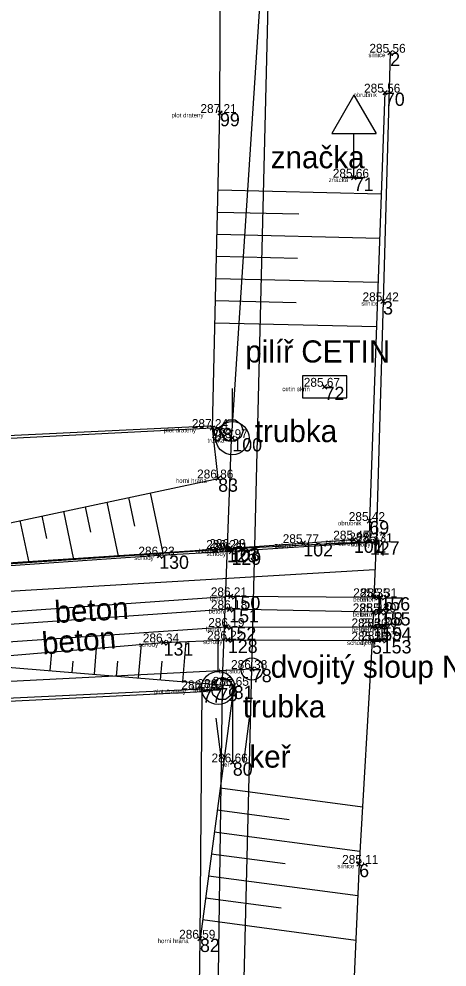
# Model space of a CAD drawing. Extents: x -456675 to -456278, y -1112395 to -1112217.
# Drawn here: x -456337.38 to -456327.72, y -1112310.69 to -1112289.29 of the extents above; entities that cross this region are included whole.
import ezdxf

# ---------------------------------------------------------------- set-up
doc = ezdxf.new("R2010")
doc.units = 0
for name, color, linetype in [('Cislo_bodu', 7, 'Continuous'), ('g_beton', 7, 'Continuous'), ('g_CETIN', 7, 'Continuous'), ('g_dopravni_znaceni', 7, 'Continuous'), ('g_elektrina', 7, 'Continuous'), ('g_katastr_stabilizace', 7, 'Continuous'), ('g_komunikace', 7, 'Continuous'), ('g_obrubnik', 7, 'Continuous'), ('g_ploty', 7, 'Continuous'), ('g_schody', 7, 'Continuous'), ('g_terenni_hrany', 7, 'Continuous'), ('g_vegetace', 7, 'Continuous'), ('g_zabradli', 7, 'Continuous'), ('Katastralni_mapa', 7, 'Continuous'), ('Kod_bodu', 7, 'Continuous'), ('Vyska_bodu', 7, 'Continuous'), ('Znacka_bodu', 7, 'Continuous')]:
    doc.layers.add(name, color=color, linetype=linetype)

msp = doc.modelspace()

# ---------------------------------------------------------------- linework, layer by layer
at = {"layer": 'g_beton'}
for points in [[(-456344.443, -1112303.14), (-456341.853, -1112302.97), (-456340.193, -1112302.85), (-456332.603, -1112302.32), (-456329.373, -1112302.34)], [(-456329.383, -1112302.68), (-456332.633, -1112302.61), (-456340.183, -1112303.14), (-456341.853, -1112303.27), (-456344.443, -1112303.43)], [(-456344.433, -1112303.79), (-456341.843, -1112303.66), (-456340.153, -1112303.52), (-456332.693, -1112303.01), (-456329.403, -1112303.02)]]:
    msp.add_lwpolyline(points, dxfattribs=at)
at = {"layer": 'g_CETIN'}
msp.add_lwpolyline([(-456330.983, -1112297.84), (-456329.983, -1112297.84), (-456329.983, -1112297.34), (-456330.983, -1112297.34)], close=True, dxfattribs=at)
at = {"layer": 'g_dopravni_znaceni'}
for p, q in [((-456329.823, -1112291.004), (-456330.323, -1112291.87)), ((-456329.823, -1112291.004), (-456329.323, -1112291.87)), ((-456330.323, -1112291.87), (-456329.323, -1112291.87)), ((-456329.823, -1112292.87), (-456329.823, -1112291.87)), ((-456330.073, -1112292.87), (-456329.573, -1112292.87))]:
    msp.add_line(p, q, dxfattribs=at)
at = {"layer": 'g_elektrina'}
msp.add_line((-456361.003, -1112305.42), (-456332.123, -1112303.96), dxfattribs=at)
msp.add_lwpolyline([(-456332.513, -1112319.78), (-456332.123, -1112303.96), (-456331.453, -1112276.72)], dxfattribs=at)
msp.add_circle((-456332.123, -1112303.96), 0.25, dxfattribs=at)
at = {"layer": 'g_katastr_stabilizace'}
for p, q in [((-456332.563, -1112298.376), (-456332.563, -1112297.626)), ((-456332.883, -1112304.015), (-456332.883, -1112303.265))]:
    msp.add_line(p, q, dxfattribs=at)
for centre, radius in [((-456332.563, -1112298.751), 0.375), ((-456332.563, -1112298.751), 0.0005), ((-456332.883, -1112304.39), 0.375), ((-456332.883, -1112304.39), 0.0005)]:
    msp.add_circle(centre, radius, dxfattribs=at)
at = {"layer": 'g_komunikace'}
msp.add_lwpolyline([(-456329.003, -1112290.05), (-456329.163, -1112295.66), (-456329.323, -1112301.1), (-456329.373, -1112302.34), (-456329.223, -1112302.34), (-456329.213, -1112302.68), (-456329.383, -1112302.68), (-456329.403, -1112303.02), (-456329.193, -1112303.02), (-456329.193, -1112303.31), (-456329.413, -1112303.32), (-456329.703, -1112308.36), (-456330.013, -1112315.33)], dxfattribs=at)
at = {"layer": 'g_obrubnik'}
for p, q in [((-456329.123, -1112290.95), (-456329.473, -1112300.62)), ((-456329.473, -1112300.62), (-456329.463, -1112301.08))]:
    msp.add_line(p, q, dxfattribs=at)
msp.add_lwpolyline([(-456347.483, -1112302.26), (-456344.233, -1112302.04), (-456332.683, -1112301.25), (-456329.463, -1112301.08)], dxfattribs=at)
at = {"layer": 'g_ploty'}
for points in [[(-456357.813, -1112299.7), (-456346.273, -1112299.18), (-456339.333, -1112298.84), (-456333.013, -1112298.52), (-456332.843, -1112291.41), (-456332.833, -1112287.66)], [(-456333.393, -1112317.5), (-456333.293, -1112310.05), (-456333.243, -1112304.42), (-456339.393, -1112304.71), (-456347.913, -1112305.1), (-456359.473, -1112305.79)]]:
    msp.add_lwpolyline(points, dxfattribs=at)
at = {"layer": 'g_schody'}
msp.add_line((-456329.348, -1112301.72), (-456344.478, -1112302.62), dxfattribs=at)
msp.add_lwpolyline([(-456329.323, -1112301.1), (-456332.583, -1112301.31), (-456334.213, -1112301.4), (-456340.273, -1112301.82), (-456341.953, -1112301.93), (-456344.513, -1112302.1), (-456344.443, -1112303.14), (-456344.443, -1112303.43), (-456344.433, -1112303.79), (-456344.453, -1112304.12), (-456341.853, -1112303.96), (-456340.143, -1112303.85), (-456339.183, -1112303.79), (-456334.113, -1112303.36), (-456332.663, -1112303.3), (-456329.413, -1112303.32)], dxfattribs=at)
at = {"layer": 'g_terenni_hrany'}
for p, q in [((-456329.206, -1112293.241), (-456332.885, -1112293.153)), ((-456331.061, -1112293.697), (-456332.897, -1112293.653)), ((-456329.242, -1112294.24), (-456332.909, -1112294.153)), ((-456331.091, -1112294.696), (-456332.921, -1112294.653)), ((-456329.279, -1112295.24), (-456332.933, -1112295.152)), ((-456331.121, -1112295.696), (-456332.945, -1112295.652)), ((-456329.315, -1112296.239), (-456332.957, -1112296.152)), ((-456334.122, -1112301.348), (-456334.412, -1112299.986)), ((-456335.756, -1112300.875), (-456335.879, -1112300.298)), ((-456335.13, -1112301.417), (-456335.39, -1112300.194)), ((-456334.764, -1112300.736), (-456334.901, -1112300.09)), ((-456336.749, -1112301.013), (-456336.857, -1112300.506)), ((-456336.137, -1112301.486), (-456336.368, -1112300.402)), ((-456337.145, -1112301.555), (-456337.346, -1112300.61)), ((-456335.635, -1112303.489), (-456335.684, -1112304.079)), ((-456334.624, -1112303.403), (-456334.687, -1112304.162)), ((-456333.615, -1112303.339), (-456333.69, -1112304.244)), ((-456336.645, -1112303.575), (-456336.68, -1112303.997)), ((-456336.161, -1112303.785), (-456336.182, -1112304.038)), ((-456335.157, -1112303.783), (-456335.185, -1112304.121)), ((-456334.154, -1112303.782), (-456334.189, -1112304.203)), ((-456329.63, -1112307.08), (-456332.841, -1112306.653)), ((-456331.283, -1112307.365), (-456332.907, -1112307.149)), ((-456329.687, -1112308.082), (-456332.973, -1112307.644)), ((-456331.376, -1112308.361), (-456333.039, -1112308.14)), ((-456329.736, -1112309.084), (-456333.105, -1112308.636)), ((-456331.464, -1112309.358), (-456333.171, -1112309.131)), ((-456329.78, -1112310.087), (-456333.237, -1112309.627))]:
    msp.add_line(p, q, dxfattribs=at)
for points in [[(-456341.973, -1112301.85), (-456338.143, -1112300.78), (-456332.883, -1112299.66), (-456333.013, -1112298.52)], [(-456339.183, -1112303.79), (-456332.533, -1112304.34), (-456333.293, -1112310.05)]]:
    msp.add_lwpolyline(points, dxfattribs=at)
at = {"layer": 'g_vegetace'}
for p, q in [((-456332.553, -1112306.07), (-456332.553, -1112304.57)), ((-456332.803, -1112306.07), (-456332.928, -1112305.07)), ((-456332.303, -1112306.07), (-456332.178, -1112305.07))]:
    msp.add_line(p, q, dxfattribs=at)
at = {"layer": 'g_zabradli'}
msp.add_lwpolyline([(-456344.563, -1112302.04), (-456341.973, -1112301.85), (-456332.613, -1112301.23), (-456330.963, -1112301.12), (-456329.823, -1112301.04)], dxfattribs=at)
at = {"layer": 'Katastralni_mapa'}
for points in [[(-456331.863, -1112287.61), (-456332.573, -1112298.58)], [(-456333.073, -1112298.48), (-456362.193, -1112299.87)], [(-456332.573, -1112298.58), (-456333.073, -1112298.48)], [(-456332.793, -1112304.41), (-456332.573, -1112298.58)], [(-456332.598, -1112298.58), (-456332.548, -1112298.58)], [(-456347.903, -1112305.2), (-456333.213, -1112304.47)], [(-456333.213, -1112304.47), (-456332.793, -1112304.41)], [(-456332.793, -1112304.41), (-456333.173, -1112331.27)], [(-456332.818, -1112304.41), (-456332.768, -1112304.41)]]:
    msp.add_lwpolyline(points, dxfattribs=at)
for points in [[(-456332.498, -1112298.34), (-456332.373, -1112298.435), (-456332.323, -1112298.58), (-456332.373, -1112298.725), (-456332.498, -1112298.82), (-456332.648, -1112298.82), (-456332.773, -1112298.725), (-456332.823, -1112298.58), (-456332.773, -1112298.435), (-456332.648, -1112298.34)], [(-456332.718, -1112304.17), (-456332.593, -1112304.265), (-456332.543, -1112304.41), (-456332.593, -1112304.555), (-456332.718, -1112304.65), (-456332.868, -1112304.65), (-456332.993, -1112304.555), (-456333.043, -1112304.41), (-456332.993, -1112304.265), (-456332.868, -1112304.17)]]:
    msp.add_lwpolyline(points, close=True, dxfattribs=at)
at = {"layer": 'Znacka_bodu'}
for p, q in [((-456329.003, -1112290.05), (-456329.053, -1112290)), ((-456329.003, -1112290.05), (-456328.953, -1112290)), ((-456329.003, -1112290.05), (-456329.053, -1112290.1)), ((-456329.003, -1112290.05), (-456328.953, -1112290.1)), ((-456329.123, -1112290.95), (-456329.173, -1112290.9)), ((-456329.123, -1112290.95), (-456329.173, -1112291)), ((-456329.123, -1112290.95), (-456329.073, -1112290.9)), ((-456329.123, -1112290.95), (-456329.073, -1112291)), ((-456332.843, -1112291.41), (-456332.893, -1112291.36)), ((-456332.843, -1112291.41), (-456332.893, -1112291.46)), ((-456332.843, -1112291.41), (-456332.793, -1112291.36)), ((-456332.843, -1112291.41), (-456332.793, -1112291.46)), ((-456329.823, -1112292.87), (-456329.873, -1112292.82)), ((-456329.823, -1112292.87), (-456329.873, -1112292.92)), ((-456329.823, -1112292.87), (-456329.773, -1112292.82)), ((-456329.823, -1112292.87), (-456329.773, -1112292.92)), ((-456329.163, -1112295.66), (-456329.213, -1112295.61)), ((-456329.163, -1112295.66), (-456329.213, -1112295.71)), ((-456329.163, -1112295.66), (-456329.113, -1112295.61)), ((-456329.163, -1112295.66), (-456329.113, -1112295.71)), ((-456330.483, -1112297.59), (-456330.533, -1112297.54)), ((-456330.483, -1112297.59), (-456330.533, -1112297.64)), ((-456330.483, -1112297.59), (-456330.433, -1112297.54)), ((-456330.483, -1112297.59), (-456330.433, -1112297.64)), ((-456333.013, -1112298.52), (-456333.063, -1112298.47)), ((-456333.013, -1112298.52), (-456333.063, -1112298.57)), ((-456333.013, -1112298.52), (-456332.963, -1112298.47)), ((-456333.013, -1112298.52), (-456332.963, -1112298.57)), ((-456332.563, -1112298.75), (-456332.613, -1112298.7)), ((-456332.563, -1112298.75), (-456332.613, -1112298.8)), ((-456332.563, -1112298.75), (-456332.513, -1112298.7)), ((-456332.563, -1112298.75), (-456332.513, -1112298.8)), ((-456332.883, -1112299.66), (-456332.933, -1112299.61)), ((-456332.883, -1112299.66), (-456332.833, -1112299.61)), ((-456332.883, -1112299.66), (-456332.933, -1112299.71)), ((-456332.883, -1112299.66), (-456332.833, -1112299.71)), ((-456329.473, -1112300.62), (-456329.523, -1112300.57)), ((-456329.473, -1112300.62), (-456329.523, -1112300.67)), ((-456329.473, -1112300.62), (-456329.423, -1112300.57)), ((-456329.473, -1112300.62), (-456329.423, -1112300.67)), ((-456330.963, -1112301.12), (-456331.013, -1112301.07)), ((-456330.963, -1112301.12), (-456331.013, -1112301.17)), ((-456330.963, -1112301.12), (-456330.913, -1112301.07)), ((-456330.963, -1112301.12), (-456330.913, -1112301.17)), ((-456329.823, -1112301.04), (-456329.873, -1112300.99)), ((-456329.823, -1112301.04), (-456329.873, -1112301.09)), ((-456329.823, -1112301.04), (-456329.773, -1112300.99)), ((-456329.823, -1112301.04), (-456329.773, -1112301.09)), ((-456329.463, -1112301.08), (-456329.513, -1112301.03)), ((-456329.463, -1112301.08), (-456329.513, -1112301.13)), ((-456329.463, -1112301.08), (-456329.413, -1112301.03)), ((-456329.463, -1112301.08), (-456329.413, -1112301.13)), ((-456329.323, -1112301.1), (-456329.373, -1112301.05)), ((-456329.323, -1112301.1), (-456329.373, -1112301.15)), ((-456329.323, -1112301.1), (-456329.273, -1112301.05)), ((-456329.323, -1112301.1), (-456329.273, -1112301.15)), ((-456334.213, -1112301.4), (-456334.263, -1112301.35)), ((-456334.213, -1112301.4), (-456334.163, -1112301.35)), ((-456332.683, -1112301.25), (-456332.733, -1112301.2)), ((-456332.683, -1112301.25), (-456332.733, -1112301.3)), ((-456332.683, -1112301.25), (-456332.633, -1112301.2)), ((-456332.683, -1112301.25), (-456332.633, -1112301.3)), ((-456332.613, -1112301.23), (-456332.663, -1112301.18)), ((-456332.613, -1112301.23), (-456332.663, -1112301.28)), ((-456332.583, -1112301.31), (-456332.633, -1112301.26)), ((-456332.583, -1112301.31), (-456332.633, -1112301.36)), ((-456332.613, -1112301.23), (-456332.563, -1112301.18)), ((-456332.613, -1112301.23), (-456332.563, -1112301.28)), ((-456332.583, -1112301.31), (-456332.533, -1112301.26)), ((-456332.583, -1112301.31), (-456332.533, -1112301.36)), ((-456334.213, -1112301.4), (-456334.263, -1112301.45)), ((-456334.213, -1112301.4), (-456334.163, -1112301.45)), ((-456332.603, -1112302.32), (-456332.653, -1112302.27)), ((-456332.603, -1112302.32), (-456332.653, -1112302.37)), ((-456332.603, -1112302.32), (-456332.553, -1112302.27)), ((-456332.603, -1112302.32), (-456332.553, -1112302.37)), ((-456329.373, -1112302.34), (-456329.423, -1112302.29)), ((-456329.373, -1112302.34), (-456329.423, -1112302.39)), ((-456329.373, -1112302.34), (-456329.323, -1112302.29)), ((-456329.373, -1112302.34), (-456329.323, -1112302.39)), ((-456329.223, -1112302.34), (-456329.273, -1112302.29)), ((-456329.223, -1112302.34), (-456329.273, -1112302.39)), ((-456329.223, -1112302.34), (-456329.173, -1112302.29)), ((-456329.223, -1112302.34), (-456329.173, -1112302.39)), ((-456332.633, -1112302.61), (-456332.683, -1112302.56)), ((-456332.633, -1112302.61), (-456332.683, -1112302.66)), ((-456332.633, -1112302.61), (-456332.583, -1112302.56)), ((-456332.633, -1112302.61), (-456332.583, -1112302.66)), ((-456329.383, -1112302.68), (-456329.433, -1112302.63)), ((-456329.383, -1112302.68), (-456329.333, -1112302.63)), ((-456329.213, -1112302.68), (-456329.263, -1112302.63)), ((-456329.213, -1112302.68), (-456329.163, -1112302.63)), ((-456329.383, -1112302.68), (-456329.433, -1112302.73)), ((-456329.383, -1112302.68), (-456329.333, -1112302.73)), ((-456329.213, -1112302.68), (-456329.263, -1112302.73)), ((-456329.213, -1112302.68), (-456329.163, -1112302.73)), ((-456332.693, -1112303.01), (-456332.743, -1112302.96)), ((-456332.693, -1112303.01), (-456332.743, -1112303.06)), ((-456332.693, -1112303.01), (-456332.643, -1112302.96)), ((-456332.693, -1112303.01), (-456332.643, -1112303.06)), ((-456329.403, -1112303.02), (-456329.453, -1112302.97)), ((-456329.403, -1112303.02), (-456329.453, -1112303.07)), ((-456329.403, -1112303.02), (-456329.353, -1112302.97)), ((-456329.403, -1112303.02), (-456329.353, -1112303.07)), ((-456329.193, -1112303.02), (-456329.243, -1112302.97)), ((-456329.193, -1112303.02), (-456329.243, -1112303.07)), ((-456329.193, -1112303.02), (-456329.143, -1112302.97)), ((-456329.193, -1112303.02), (-456329.143, -1112303.07)), ((-456332.663, -1112303.3), (-456332.713, -1112303.25)), ((-456332.663, -1112303.3), (-456332.613, -1112303.25)), ((-456329.413, -1112303.32), (-456329.463, -1112303.27)), ((-456329.413, -1112303.32), (-456329.363, -1112303.27)), ((-456329.193, -1112303.31), (-456329.243, -1112303.26)), ((-456329.193, -1112303.31), (-456329.143, -1112303.26)), ((-456334.113, -1112303.36), (-456334.163, -1112303.31)), ((-456334.113, -1112303.36), (-456334.163, -1112303.41)), ((-456334.113, -1112303.36), (-456334.063, -1112303.31)), ((-456334.113, -1112303.36), (-456334.063, -1112303.41)), ((-456332.663, -1112303.3), (-456332.713, -1112303.35)), ((-456332.663, -1112303.3), (-456332.613, -1112303.35)), ((-456329.413, -1112303.32), (-456329.463, -1112303.37)), ((-456329.413, -1112303.32), (-456329.363, -1112303.37)), ((-456329.193, -1112303.31), (-456329.243, -1112303.36)), ((-456329.193, -1112303.31), (-456329.143, -1112303.36)), ((-456332.123, -1112303.96), (-456332.173, -1112303.91)), ((-456332.123, -1112303.96), (-456332.073, -1112303.91)), ((-456332.123, -1112303.96), (-456332.173, -1112304.01)), ((-456332.123, -1112303.96), (-456332.073, -1112304.01)), ((-456332.883, -1112304.39), (-456332.933, -1112304.34)), ((-456332.883, -1112304.39), (-456332.833, -1112304.34)), ((-456332.533, -1112304.34), (-456332.583, -1112304.29)), ((-456332.533, -1112304.34), (-456332.583, -1112304.39)), ((-456332.533, -1112304.34), (-456332.483, -1112304.29)), ((-456332.533, -1112304.34), (-456332.483, -1112304.39)), ((-456333.243, -1112304.42), (-456333.293, -1112304.37)), ((-456333.243, -1112304.42), (-456333.293, -1112304.47)), ((-456333.243, -1112304.42), (-456333.193, -1112304.37)), ((-456333.243, -1112304.42), (-456333.193, -1112304.47)), ((-456332.883, -1112304.39), (-456332.933, -1112304.44)), ((-456332.883, -1112304.39), (-456332.833, -1112304.44)), ((-456332.553, -1112306.07), (-456332.603, -1112306.02)), ((-456332.553, -1112306.07), (-456332.603, -1112306.12)), ((-456332.553, -1112306.07), (-456332.503, -1112306.02)), ((-456332.553, -1112306.07), (-456332.503, -1112306.12)), ((-456329.703, -1112308.36), (-456329.753, -1112308.31)), ((-456329.703, -1112308.36), (-456329.753, -1112308.41)), ((-456329.703, -1112308.36), (-456329.653, -1112308.31)), ((-456329.703, -1112308.36), (-456329.653, -1112308.41)), ((-456333.293, -1112310.05), (-456333.343, -1112310)), ((-456333.293, -1112310.05), (-456333.343, -1112310.1)), ((-456333.293, -1112310.05), (-456333.243, -1112310)), ((-456333.293, -1112310.05), (-456333.243, -1112310.1))]:
    msp.add_line(p, q, dxfattribs=at)

# ---------------------------------------------------------------- texts
at = {"layer": 'Cislo_bodu'}
for s, p in [('2', (-456329.003, -1112290.35)), ('70', (-456329.123, -1112291.25)), ('99', (-456332.843, -1112291.71)), ('71', (-456329.823, -1112293.17)), ('3', (-456329.163, -1112295.96)), ('72', (-456330.483, -1112297.89)), ('98', (-456333.013, -1112298.82)), ('100', (-456332.563, -1112299.05)), ('83', (-456332.883, -1112299.96)), ('69', (-456329.473, -1112300.92)), ('102', (-456330.963, -1112301.42)), ('101', (-456329.823, -1112301.34)), ('127', (-456329.463, -1112301.38)), ('4', (-456329.323, -1112301.4)), ('126', (-456332.683, -1112301.55)), ('103', (-456332.613, -1112301.53)), ('129', (-456332.583, -1112301.61)), ('130', (-456334.213, -1112301.7)), ('150', (-456332.603, -1112302.62)), ('157', (-456329.373, -1112302.64)), ('156', (-456329.223, -1112302.64)), ('151', (-456332.633, -1112302.91)), ('158', (-456329.383, -1112302.98)), ('155', (-456329.213, -1112302.98)), ('152', (-456332.693, -1112303.31)), ('159', (-456329.403, -1112303.32)), ('154', (-456329.193, -1112303.32)), ('128', (-456332.663, -1112303.6)), ('131', (-456334.113, -1112303.66)), ('5', (-456329.413, -1112303.62)), ('153', (-456329.193, -1112303.61)), ('78', (-456332.123, -1112304.26)), ('81', (-456332.533, -1112304.64)), ('77', (-456333.243, -1112304.72)), ('79', (-456332.883, -1112304.69)), ('80', (-456332.553, -1112306.37)), ('6', (-456329.703, -1112308.66)), ('82', (-456333.293, -1112310.35))]:
    msp.add_text(s, height=0.3, dxfattribs=at).set_placement(p)
at = {"layer": 'g_beton'}
for rotation, p in [(3.2894, (-456336.562, -1112302.926)), (4.8107, (-456336.838, -1112303.634))]:
    msp.add_text('beton', height=0.5, rotation=rotation, dxfattribs=at).set_placement(p)
at = {"layer": 'g_CETIN'}
msp.add_text('pilíř CETIN', height=0.5, dxfattribs=at).set_placement((-456332.272, -1112297.043))
at = {"layer": 'g_dopravni_znaceni'}
msp.add_text('značka', height=0.5, dxfattribs=at).set_placement((-456331.699, -1112292.658))
at = {"layer": 'g_elektrina'}
msp.add_text('dvojitý sloup NN', height=0.5, dxfattribs=at).set_placement((-456331.699, -1112304.158))
at = {"layer": 'g_katastr_stabilizace'}
for p in [(-456332.058, -1112298.84), (-456332.327, -1112305.055)]:
    msp.add_text('trubka', height=0.5, dxfattribs=at).set_placement(p)
at = {"layer": 'g_vegetace'}
msp.add_text('keř', height=0.5, dxfattribs=at).set_placement((-456332.181, -1112306.188))
at = {"layer": 'Kod_bodu'}
for s, p in [('silnice', (-456329.494, -1112290.15)), ('obrubnik', (-456329.834, -1112291.05)), ('plot drateny', (-456333.936, -1112291.51)), ('znacka', (-456330.39, -1112292.97)), ('silnice', (-456329.654, -1112295.76)), ('cetin skrin', (-456331.438, -1112297.69)), ('plot drateny', (-456334.106, -1112298.62)), ('trubka', (-456333.125, -1112298.85)), ('horni hrana', (-456333.839, -1112299.76)), ('obrubnik', (-456330.184, -1112300.72)), ('zabradli', (-456331.606, -1112301.22)), ('zabradli', (-456330.466, -1112301.14)), ('obrubnik', (-456330.174, -1112301.18)), ('schody', (-456329.886, -1112301.2)), ('obrubnik', (-456333.394, -1112301.35)), ('zabradli', (-456333.256, -1112301.33)), ('schody', (-456333.146, -1112301.41)), ('schody', (-456334.776, -1112301.5)), ('beton', (-456333.069, -1112302.42)), ('beton', (-456329.839, -1112302.44)), ('beton', (-456329.689, -1112302.44)), ('beton', (-456333.099, -1112302.71)), ('beton', (-456329.849, -1112302.78)), ('beton', (-456329.679, -1112302.78)), ('beton', (-456333.159, -1112303.11)), ('beton', (-456329.869, -1112303.12)), ('beton', (-456329.659, -1112303.12)), ('schody', (-456333.226, -1112303.4)), ('schody', (-456334.676, -1112303.46)), ('schody', (-456329.976, -1112303.42)), ('beton', (-456329.659, -1112303.41)), ('bet.sloup', (-456332.863, -1112304.06)), ('horni hrana', (-456333.489, -1112304.44)), ('plot drateny', (-456334.336, -1112304.52)), ('trubka', (-456333.445, -1112304.49)), ('ker', (-456332.82, -1112306.17)), ('silnice', (-456330.194, -1112308.46)), ('horni hrana', (-456334.249, -1112310.15))]:
    msp.add_text(s, height=0.1, dxfattribs=at).set_placement(p)
at = {"layer": 'Vyska_bodu'}
for s, p in [('285.56', (-456329.473, -1112290.05)), ('285.56', (-456329.593, -1112290.95)), ('287.21', (-456333.284, -1112291.41)), ('285.66', (-456330.299, -1112292.87)), ('285.42', (-456329.628, -1112295.66)), ('285.67', (-456330.953, -1112297.59)), ('287.24', (-456333.478, -1112298.52)), ('286.97', (-456333.034, -1112298.75)), ('286.86', (-456333.359, -1112299.66)), ('285.42', (-456329.938, -1112300.62)), ('285.77', (-456331.428, -1112301.12)), ('285.47', (-456330.288, -1112301.04)), ('285.37', (-456329.928, -1112301.08)), ('285.31', (-456329.764, -1112301.1)), ('286.24', (-456333.153, -1112301.25)), ('286.23', (-456333.083, -1112301.23)), ('286.21', (-456333.03, -1112301.31)), ('286.23', (-456334.683, -1112301.4)), ('286.21', (-456333.05, -1112302.32)), ('285.35', (-456329.838, -1112302.34)), ('285.31', (-456329.664, -1112302.34)), ('286.18', (-456333.047, -1112302.61)), ('285.34', (-456329.848, -1112302.68)), ('285.30', (-456329.687, -1112302.68)), ('286.19', (-456333.108, -1112303.01)), ('285.30', (-456329.877, -1112303.02)), ('285.30', (-456329.667, -1112303.02)), ('286.34', (-456334.583, -1112303.36)), ('286.22', (-456333.133, -1112303.3)), ('285.28', (-456329.878, -1112303.32)), ('285.27', (-456329.658, -1112303.31)), ('286.38', (-456332.593, -1112303.96)), ('286.65', (-456333.009, -1112304.34)), ('286.78', (-456333.713, -1112304.42)), ('286.77', (-456333.353, -1112304.39)), ('286.66', (-456333.034, -1112306.07)), ('285.11', (-456330.088, -1112308.36)), ('286.59', (-456333.764, -1112310.05))]:
    msp.add_text(s, height=0.2, dxfattribs=at).set_placement(p)

doc.saveas('drawing.dxf')
